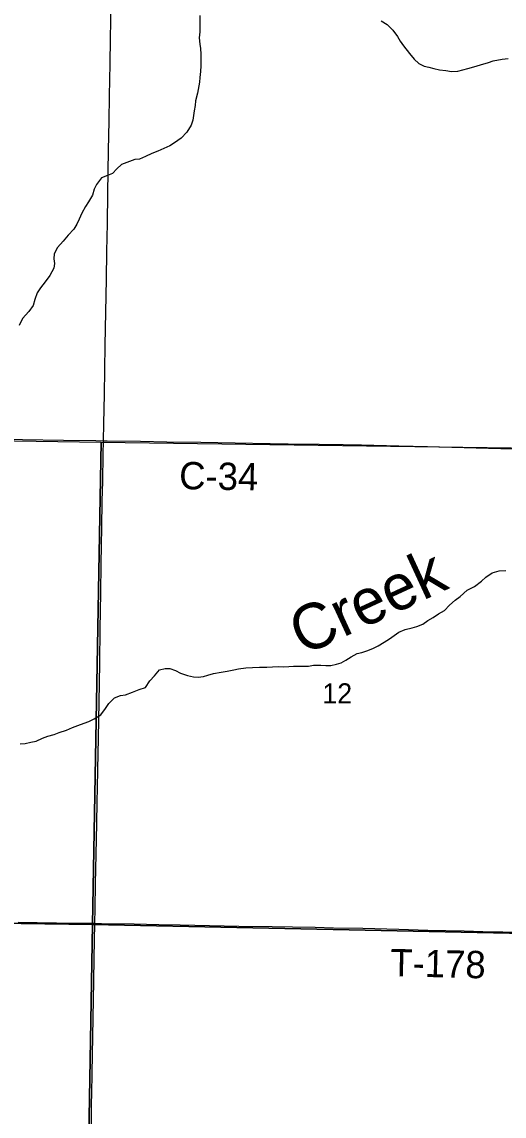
# Model space of a CAD drawing. Extents: x -8.5 to 18.7, y -20.3 to 7.
# Drawn here: x 9.055 to 11.064, y -15.596 to -11.043 of the extents above; entities that cross this region are included whole.
import ezdxf

# ---------------------------------------------------------------- set-up
doc = ezdxf.new("R2010")
doc.units = 0
for name, color, linetype in [('GM_X_County_Road', 7, 'Continuous'), ('GM_X_County_Road_Text', 7, 'Continuous'), ('GM_X_Minor_River', 7, 'Continuous'), ('GM_X_Minor_River_Text', 7, 'Continuous'), ('GM_X_Section', 7, 'Continuous'), ('GM_X_Section_Text', 7, 'Continuous'), ('GM_X_Township_Road', 7, 'Continuous'), ('GM_X_Township_Road_Text', 7, 'Continuous')]:
    doc.layers.add(name, color=color, linetype=linetype)

msp = doc.modelspace()

# ---------------------------------------------------------------- linework, layer by layer
at = {"layer": 'GM_X_County_Road'}
for points in [[(9.3952, -12.7854), (9.3965, -12.7135), (9.399, -12.5929), (9.4024, -12.3878), (9.4077, -12.1131), (9.4089, -11.9987), (9.4117, -11.8819), (9.4137, -11.7551), (9.4169, -11.5761), (9.4188, -11.4555), (9.421, -11.3511), (9.4231, -11.2168), (9.4249, -11.1136), (9.4263, -11.0378), (9.4299, -10.8525), (9.43, -10.8203), (9.43, -10.8073)], [(7.4089, -12.7537), (7.4409, -12.7539), (7.6261, -12.7579), (7.881, -12.761), (7.9345, -12.7618), (8.0277, -12.7639), (8.1408, -12.7654), (8.3012, -12.7687), (8.4852, -12.7714), (8.5834, -12.7731), (8.9141, -12.7783), (9.0583, -12.7805), (9.2286, -12.7829), (9.3629, -12.7848), (9.3952, -12.7854)], [(9.3599, -14.7935), (9.361, -14.7322), (9.3625, -14.629), (9.3648, -14.506), (9.3676, -14.3792), (9.3691, -14.2872), (9.3705, -14.2313), (9.3721, -14.1542), (9.3741, -14.0237), (9.3779, -13.8721), (9.3791, -13.795), (9.3804, -13.708), (9.3818, -13.57), (9.384, -13.4183), (9.3861, -13.299), (9.3868, -13.2194), (9.3879, -13.1473), (9.3902, -13.0354), (9.3922, -12.9547), (9.3941, -12.8415), (9.3952, -12.7854)], [(9.3952, -12.7854), (9.4101, -12.7857), (9.5493, -12.7876), (9.6587, -12.7897), (9.8004, -12.7914), (9.9434, -12.794), (10.0901, -12.7965), (10.1647, -12.7978), (10.294, -12.7998), (10.3934, -12.8011), (10.4693, -12.803), (10.6246, -12.8072), (10.7452, -12.8101), (10.9478, -12.8152), (11.1019, -12.8186), (11.2039, -12.8213), (11.2573, -12.8227), (11.3019, -12.8225), (11.3416, -12.8204), (11.3775, -12.8175), (11.4034, -12.8145)], [(9.3259, -16.7991), (9.326, -16.7709), (9.3266, -16.6901), (9.3279, -16.6018), (9.3308, -16.4216), (9.335, -16.1655), (9.3375, -16.0536), (9.3386, -15.9952), (9.3398, -15.9069), (9.3425, -15.7689), (9.3454, -15.6123), (9.3458, -15.5439), (9.3465, -15.5029), (9.3479, -15.4171), (9.3498, -15.3413), (9.3554, -15.0343), (9.3572, -14.9385), (9.3599, -14.7935)]]:
    msp.add_lwpolyline(points, dxfattribs=at)
at = {"layer": 'GM_X_Minor_River'}
for points in [[(9.7962, -11.0167), (9.7961, -11.0835), (9.7945, -11.1093), (9.796, -11.1351), (9.799, -11.1541), (9.8012, -11.1776), (9.8011, -11.2262), (9.7996, -11.2498), (9.7972, -11.2748), (9.7957, -11.2938), (9.7865, -11.3393), (9.7788, -11.3712), (9.7765, -11.3909), (9.7727, -11.4129), (9.7703, -11.4327), (9.768, -11.4517), (9.7604, -11.4729), (9.7429, -11.5017), (9.7186, -11.5267), (9.6912, -11.5457), (9.6715, -11.5578), (9.6464, -11.5699), (9.6221, -11.5804), (9.5971, -11.5903), (9.5697, -11.6031), (9.5454, -11.6137), (9.5264, -11.6159), (9.4703, -11.6364)], [(10.5518, -11.0387), (10.5768, -11.0539), (10.6002, -11.0775), (10.6191, -11.1041), (10.6305, -11.1231), (10.6441, -11.1429), (10.6691, -11.1741), (10.6887, -11.1977), (10.7084, -11.2159), (10.7312, -11.2266), (10.7501, -11.2312), (10.7706, -11.2373), (10.7941, -11.2419), (10.8206, -11.245), (10.8441, -11.2496), (10.8714, -11.2474), (10.8912, -11.2429), (10.9132, -11.2368), (10.9382, -11.23), (10.9648, -11.2217), (10.999, -11.2112), (11.0179, -11.2052), (11.0559, -11.1976), (11.0802, -11.1946)], [(9.4703, -11.6364), (9.4514, -11.6546), (9.4324, -11.6742), (9.4127, -11.6825), (9.3869, -11.6915), (9.3664, -11.7187), (9.3564, -11.7391), (9.3495, -11.7634), (9.3335, -11.7914), (9.3205, -11.811), (9.3053, -11.8383), (9.2938, -11.864), (9.2839, -11.8845), (9.2717, -11.9057), (9.2489, -11.9306), (9.2268, -11.9555), (9.204, -11.982), (9.1902, -12.0085), (9.1886, -12.0282), (9.1916, -12.0479), (9.1893, -12.0669), (9.1717, -12.0979), (9.1527, -12.1244), (9.1336, -12.1493), (9.1199, -12.1705), (9.1092, -12.1985), (9.103, -12.2228), (9.084, -12.2477), (9.0581, -12.2764), (9.0444, -12.306)], [(9.0482, -14.0473), (9.0687, -14.0451), (9.093, -14.0399), (9.1149, -14.0354), (9.1415, -14.0234), (9.1643, -14.0152), (9.19, -14.0085), (9.2113, -14.0002), (9.2409, -13.9905), (9.2667, -13.9792), (9.2879, -13.9702), (9.3152, -13.9605), (9.3342, -13.9538), (9.3562, -13.9432), (9.3843, -13.9267), (9.4041, -13.9002), (9.417, -13.879), (9.4414, -13.8556), (9.4657, -13.8451), (9.4869, -13.8422), (9.5157, -13.8324), (9.5445, -13.8204), (9.5703, -13.8122), (9.5886, -13.785), (9.6076, -13.7631), (9.6289, -13.7389), (9.6517, -13.7329), (9.6721, -13.7338), (9.6956, -13.7422), (9.716, -13.753), (9.7455, -13.763), (9.7697, -13.7676), (9.7902, -13.7692), (9.8114, -13.7671), (9.8304, -13.7603), (9.8539, -13.7544), (9.8849, -13.7492), (9.9107, -13.7448), (9.9388, -13.7388), (9.9577, -13.7351), (9.988, -13.7307), (10.0161, -13.7286), (10.0449, -13.7272), (10.0759, -13.7273), (10.0994, -13.7267), (10.1229, -13.7253), (10.1433, -13.7269), (10.1676, -13.7255), (10.1873, -13.724), (10.229, -13.7242), (10.2494, -13.7236), (10.2706, -13.7191), (10.3009, -13.72), (10.3214, -13.7209), (10.3426, -13.7202), (10.3653, -13.7158), (10.3851, -13.709), (10.4048, -13.6985), (10.4261, -13.6849), (10.4519, -13.6707), (10.4708, -13.6662), (10.4966, -13.658), (10.5201, -13.6482), (10.5391, -13.6384), (10.5649, -13.6241), (10.5869, -13.6098), (10.6059, -13.5955), (10.6257, -13.5827), (10.6522, -13.5707), (10.6811, -13.564), (10.7008, -13.558), (10.7251, -13.5483), (10.7463, -13.5339), (10.7683, -13.5211), (10.7904, -13.5061), (10.8154, -13.4918), (10.836, -13.4699), (10.8595, -13.4487), (10.8808, -13.4337), (10.9104, -13.4072), (10.94, -13.3914), (10.9689, -13.3703), (10.9879, -13.3537), (11.0137, -13.3356), (11.0433, -13.3274), (11.0706, -13.326)]]:
    msp.add_lwpolyline(points, dxfattribs=at)
at = {"layer": 'GM_X_Section'}
for points in [[(7.3966, -12.7605), (9.3854, -12.792), (9.3493, -14.7982), (7.3681, -14.7705)], [(9.3854, -12.792), (11.3947, -12.819), (11.3525, -14.8313), (11.3525, -14.8396), (9.3493, -14.7982)], [(7.3681, -14.7705), (9.3493, -14.7982), (9.3147, -16.8052), (7.3365, -16.776)], [(9.3493, -14.7982), (11.3525, -14.8396), (11.3171, -16.8542), (9.3147, -16.8052)]]:
    msp.add_lwpolyline(points, close=True, dxfattribs=at)
at = {"layer": 'GM_X_Township_Road'}
for points in [[(9.04, -14.7889), (9.2004, -14.791), (9.3185, -14.7934), (9.3599, -14.7935)], [(9.3599, -14.7935), (9.3869, -14.7937), (9.5236, -14.796), (9.6255, -14.798), (9.715, -14.7997), (9.9587, -14.8048), (10.0979, -14.8067), (10.1824, -14.8084), (10.2769, -14.8098), (10.3527, -14.8117), (10.4758, -14.8141), (10.625, -14.8178), (10.7455, -14.8216), (10.8972, -14.8251), (10.9754, -14.8278), (11.0587, -14.8296), (11.1768, -14.8334), (11.2526, -14.835), (11.2975, -14.8351), (11.3311, -14.8337), (11.3623, -14.831)]]:
    msp.add_lwpolyline(points, dxfattribs=at)

# ---------------------------------------------------------------- texts
at = {"layer": 'GM_X_County_Road_Text'}
msp.add_text('C-34', height=0.11364, rotation=358.9769, dxfattribs=at).set_placement((9.7098, -12.9868))
at = {"layer": 'GM_X_Minor_River_Text'}
msp.add_text('Creek', height=0.18949, rotation=24.7799, dxfattribs=at).set_placement((10.2264, -13.6817))
at = {"layer": 'GM_X_Section_Text'}
msp.add_text('12', height=0.08371, rotation=0, dxfattribs=at).set_placement((10.3065, -13.8786))
at = {"layer": 'GM_X_Township_Road_Text'}
msp.add_text('T-178', height=0.11364, rotation=358.6038, dxfattribs=at).set_placement((10.5887, -15.0132))

doc.saveas('drawing.dxf')
